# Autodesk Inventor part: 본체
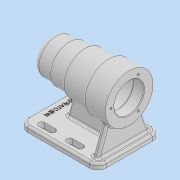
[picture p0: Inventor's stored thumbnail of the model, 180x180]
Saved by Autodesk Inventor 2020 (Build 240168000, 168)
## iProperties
Created: 2021-10
Part Number: 본체
Material: 일반
Document SubType Name: Modeling
Designer: user
Density: 1 g/cm^3
Appearance: 기본값
Mass: 255.647 g
Surface Area: 701.718 cm^2
Volume: 255.647 cm^3
Author: user
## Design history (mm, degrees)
sketch "스케치1"
  geometry: L1 (-56, 0)-(56, 0); L2 (-56, 25)-(-32, 25); L3 (-56, 0)-(-56, 25); L4 (-32, 25)-(-32, 27); L5 (-32, 27)-(-10, 27); L6 (-10, 27)-(-10, 30); L7 (-10, 30)-(24, 30); L8 (24, 30)-(24, 34); L9 (24, 34)-(56, 34); L10 (56, 34)-(56, 21); L11 (56, 21)-(41, 21); L12 (41, 21)-(41, 24); L13 (41, 24)-(-13, 24); L14 (-13, 24)-(-13, 21); L15 (-13, 21)-(-25, 21); L16 (-25, 21)-(-25, 17.5); L17 (-25, 17.5)-(-43, 17.5); L18 (-43, 17.5)-(-43, 16); L19 (-43, 16)-(-47, 16); L20 (-47, 16)-(-47, 10.5); L21 (-47, 10.5)-(-50, 10.5); L22 (-50, 10.5)-(-50, 0); L23 (-56, 0)-(-50, 0); 3 further points
  constraints: 46 end point, 16 perpendicular, 3 horizontal, 3 vertical, 1 coincident, 1 midpoint
  dimensions: "d0" = 112 distance of L1.start L1.end; "d1" = 21 diameter of L21 L1; "d2" = 32 diameter of L19 L1; "d3" = 35 diameter of L17 L1; "d4" = 42 diameter of L15 L1; "d5" = 48 diameter of L13 L1; "d6" = 42 diameter of L11 L1; "d7" = 50 diameter of L2 L1; "d8" = 54 diameter of L5 L1; "d9" = 60 diameter of L7 L1; "d10" = 68 diameter of L9 L1; "d11" = 24 distance between parallel lines of L4 L3; "d12" = 46 distance between parallel lines of L6 L3; "d13" = 80 distance between parallel lines of L8 L3; "d14" = 112 distance between parallel lines of L10 L3; "d15" = 3 distance between parallel lines of L20 L22; "d16" = 4 distance between parallel lines of L18 L20; "d17" = 18 distance between parallel lines of L16 L18; "d19" = 12 distance between parallel lines of L14 L16; "d20" = 54 distance between parallel lines of L12 L14; "d21" = 15 distance between parallel lines of L10 L12
revolve "회전1" sketch "스케치1" stored, may be unused: angle "d22" = 90 deg
node "작업 평면1"
sketch "스케치2"
  geometry: L1 (56, 25)-(56, -25) reference; L2 (56, 0)-(56, -45); L3 (56, -45)-(-56, -45); L4 (-56, -45)-(-56, 45); L5 (-56, 45)-(56, 45); L6 (56, 45)-(56, 0); 3 further points
  constraints: 10 end point, 2 collinear, 2 perpendicular, 1 midpoint, 1 vertical
  dimensions: "d24" = 45 distance of L2.start L2.end; "d25" = 112 distance of L2.end L3.end; "d26" = 90 distance of L3.end L4.end
extrude "돌출1" join sketch "스케치2" distance "d27" = 8; taper "d28" = 0 deg
fillet "모깎기1" dims "d29" = 12
node "작업 평면2"
sketch "스케치5"
  geometry: L1 (-24.658, 23.409)-(-62, 37); L2 (-24.658, -23.409)-(-62, -37); L3 (-62, 45)-(-62, 33) reference; L4 (-62, -33)-(-62, -45) reference; L5 (-62, 45)-(-70, 45) reference; L6 (-70, -45)-(-62, -45) reference; L7 (-62, 44.314)-(-62, -44.314) reference; L8 (-62, -44.314)-(-70, -44.314) reference; L9 (-70, -44.314)-(-70, 44.314) reference; L10 (-70, 44.314)-(-62, 44.314) reference; C1 r 21 at (0, 0) reference; A1 r 34 centre (0, 0) between (-24.658, 23.409) and (-24.658, -23.409) reference; A2 r 34 centre (0, 0) between (-24.658, 23.409) and (-24.658, -23.409) reference; 1 further point
  constraints: 4 end point, 2 point on circle, 2 point on line
  dimensions: "d31" = 8 distance from line of L5 L1.end; "d32" = 8 distance from line of L6 L2.end; "d33" = 110 deg angle of L3 L1; "d34" = 110 deg angle of L4 L2
extrude "돌출2" join sketch "스케치5" distance "d35" = 8; taper "d36" = 0 deg
node "작업 평면3"
sketch "스케치10"
  geometry: L1 (48, -24.658)-(48, -62) reference; L2 (-44, -62)-(44, -62) reference; L3 (-19.622, -27)-(-29, -62); 1 further point
  constraints: 2 end point, 1 point on line
  dimensions: "d40" = 105 deg angle of L2 L3; "d41" = 77 distance from line of L1 L3.end
feature "리브1" sketch "스케치10" dims "d42" = 1, "d43" = 8, "d44" = 0, "d45" = 0, "d46" = 1, "d47" = 1
sketch "스케치11"
  geometry: L1 (-36, -33)-(-21, -33); L2 (-36, -37.5)-(-21, -37.5); L3 (-21, -28.5)-(-36, -28.5); L4 (-56, 33)-(-56, -33) reference; L5 (40, 37)-(48, 37) reference; L6 (48, 37)-(48, -37) reference; L7 (48, -37)-(40, -37) reference; L8 (40, -37)-(40, -4) reference; L9 (40, -4)-(-29, -4) reference; L10 (-29, -4)-(-29, 4) reference; L11 (-29, 4)-(40, 4) reference; L12 (40, 4)-(40, 37) reference; L13 (-44, 45)-(44, 45) reference; L14 (56, 33)-(56, -33) reference; L15 (44, -45)-(-44, -45) reference; L16 (-56, -33)-(-56, 33) reference; L17 (40, -37)-(40, -4) reference; L18 (40, -4)-(-29, -4) reference; L19 (-29, -4)-(-29, 4) reference; L20 (-29, 4)-(40, 4) reference; L21 (40, 4)-(40, 37) reference; L22 (-44, 45)-(44, 45) reference; L23 (56, 33)-(56, -33) reference; L24 (44, -45)-(-44, -45) reference; L25 (-56, -33)-(-56, 33) reference; L26 (4, -33)-(19, -33); L27 (4, -37.5)-(19, -37.5); L28 (19, -28.5)-(4, -28.5); L29 (-36, 33)-(-21, 33); L30 (-36, 28.5)-(-21, 28.5); L31 (-21, 37.5)-(-36, 37.5); L32 (4, 33)-(19, 33); L33 (44, 45)-(-44, 45) reference; L34 (4, 28.5)-(19, 28.5); L35 (19, 37.5)-(4, 37.5); L36 (40, 37)-(48, 37) reference; L37 (48, 37)-(48, -37) reference; L38 (48, -37)-(40, -37) reference; A1 r 4.5 centre (-36, -33) between (-36, -28.5) and (-36, -37.5); A2 r 4.5 centre (-21, -33) between (-21, -37.5) and (-21, -28.5); A3 r 12 centre (-44, 33) between (-44, 45) and (-56, 33) reference; A4 r 12 centre (44, 33) between (56, 33) and (44, 45) reference; A5 r 12 centre (44, -33) between (44, -45) and (56, -33) reference; A6 r 12 centre (-44, -33) between (-56, -33) and (-44, -45) reference; A7 r 12 centre (-44, 33) between (-44, 45) and (-56, 33) reference; A8 r 12 centre (44, 33) between (56, 33) and (44, 45) reference; A9 r 12 centre (44, -33) between (44, -45) and (56, -33) reference; A10 r 12 centre (-44, -33) between (-56, -33) and (-44, -45) reference; A11 r 4.5 centre (4, -33) between (4, -28.5) and (4, -37.5); A12 r 4.5 centre (19, -33) between (19, -37.5) and (19, -28.5); A13 r 4.5 centre (-36, 33) between (-36, 37.5) and (-36, 28.5); A14 r 4.5 centre (-21, 33) between (-21, 28.5) and (-21, 37.5); A15 r 4.5 centre (4, 33) between (4, 37.5) and (4, 28.5); A16 r 4.5 centre (19, 33) between (19, 28.5) and (19, 37.5); 5 further points
  constraints: 32 end point, 16 point on circle, 16 tangent, 8 centre point, 5 parallel, 4 midpoint, 2 horizontal, 2 point on line
  dimensions: "d48" = 9 diameter of A2; "d49" = 20 distance from line of L4 L1.start; "d50" = 33 vertical distance of point (0, 0) point (-28.5, -33); "d51" = 15 distance of L3.start L3.end; "d52" = 15 distance of L26.start L26.end; "d53" = 9 diameter of A12; "d54" = 60 distance from line of L4 L26.start; "d55" = 15 distance of L29.start L29.end; "d56" = 9 diameter of A14; "d57" = 20 distance from line of L4 L29.start; "d58" = 33 vertical distance of point (0, 0) L29.start; "d59" = 33 vertical distance of point (0, 0) point (11.5, 33); "d60" = 60 distance from line of L4 L32.start; "d61" = 4.5 radius of A16; "d62" = 67.5 distance from line of L4 point (11.5, 33)
extrude "돌출3" cut sketch "스케치11" distance "d63" = 93.25; taper "d64" = 0 deg
sketch "스케치13"
  geometry: 2 further points
  constraints: 1 horizontal alignment
  dimensions: "d65" = 26 distance of point (0, 0) point (-26, 0)
hole "구멍1" sketch "스케치13" at (-26, 0) diameter "d66" = 3.242; stored, may be unused: countersink angle "d70" = 90 deg, drill point angle "d72" = 118 deg; dims "d67" = 8, "d68" = 4, "d69" = 2, "d71" = 11
fillet "모깎기2" dims "d76" = 0.3
fillet "모깎기4" dims "d78" = 3
fillet "모깎기5" dims "d79" = 8
fillet "모깎기6" dims "d80" = 3
chamfer "모따기1" distance "d81" = 1; stored, may be unused: second distance "d82" = 2, angle "d83" = 45 deg
fillet "모깎기7" dims "d84" = 3
fillet "모깎기8" dims "d85" = 3
sketch "스케치14"
  geometry: L1 (-25.09, -7)-(37, -7) reference; L2 (37, -7)-(37, -32.716) reference; L3 (51, -32.716)-(51, 32.716) reference; L4 (37, 32.716)-(37, 7) reference; L5 (37, 7)-(-25.09, 7) reference; L6 (-31.302, 1)-(-31.302, -1) reference; L7 (-44, -42)-(44, -42) reference; L8 (-53, 33)-(-53, -33) reference; L9 (44, 42)-(-44, 42) reference; L10 (53, -33)-(53, 33) reference; L11 (-36, 28.5)-(-21, 28.5) reference; L12 (-21, 37.5)-(-36, 37.5) reference; L13 (4, -37.5)-(19, -37.5) reference; L14 (19, -28.5)-(4, -28.5) reference; L15 (19, 37.5)-(4, 37.5) reference; L16 (4, 28.5)-(19, 28.5) reference; L17 (-36, -37.5)-(-21, -37.5) reference; L18 (-21, -28.5)-(-36, -28.5) reference; L19 (-56, 33)-(-56, -33) reference; L20 (43, -39.101)-(45, -39.101) reference; L21 (45, 39.101)-(43, 39.101) reference; A1 r 9 centre (-44, -33) between (-53, -33) and (-44, -42) reference; A2 r 9 centre (-44, 33) between (-44, 42) and (-53, 33) reference; A3 r 9 centre (44, -33) between (44, -42) and (53, -33) reference; A4 r 9 centre (44, 33) between (53, 33) and (44, 42) reference; A5 r 4.5 centre (-21, 33) between (-21, 28.5) and (-21, 37.5) reference; A6 r 4.5 centre (-36, 33) between (-36, 37.5) and (-36, 28.5) reference; A7 r 4.5 centre (4, -33) between (4, -28.5) and (4, -37.5) reference; A8 r 4.5 centre (19, -33) between (19, -37.5) and (19, -28.5) reference; A9 r 4.5 centre (19, 33) between (19, 28.5) and (19, 37.5) reference; A10 r 4.5 centre (4, 33) between (4, 37.5) and (4, 28.5) reference; A11 r 4.5 centre (-21, -33) between (-21, -37.5) and (-21, -28.5) reference; A12 r 4.5 centre (-36, -33) between (-36, -28.5) and (-36, -37.5) reference; 2 further points
  constraints: 1 horizontal alignment, 7 other
  dimensions: "d86" = 12 distance from line of L19 point (-44, 0)
feature "엠보싱1" sketch "스케치14" dims "d0" = 112, "d1" = 21, "d2" = 32, "d3" = 35, "d4" = 42, "d5" = 48, "d6" = 42, "d7" = 50, "d8" = 54, "d9" = 60, "d10" = 68, "d11" = 24, "d12" = 46, "d13" = 80, "d14" = 112, "d15" = 3, "d16" = 4, "d17" = 18, "d19" = 12, "d20" = 54, "d21" = 15, "d87" = 0.5, "d88" = 0
fillet "모깎기9" dims "d89" = 3
fillet "모깎기10" dims "d90" = 3
node "솔리드1"
pattern_circular "원형 패턴1" dims angle "d74" = 360 deg
node "절단 모서리 투영1"
node "절단 모서리 투영4"
node "절단 모서리 투영5"
node "절단 모서리 투영6"
feature "A9D066F2-1C7D-4E18-AEED-F7BC21143FA4" dims "d66" = 3.242, "d67" = 8, "d68" = 4, "d69" = 2, "d70" = 90 deg, "d71" = 11, "d72" = 118 deg
other parameters: "d30" = 48, "d37" = 0
